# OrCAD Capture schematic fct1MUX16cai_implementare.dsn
size A
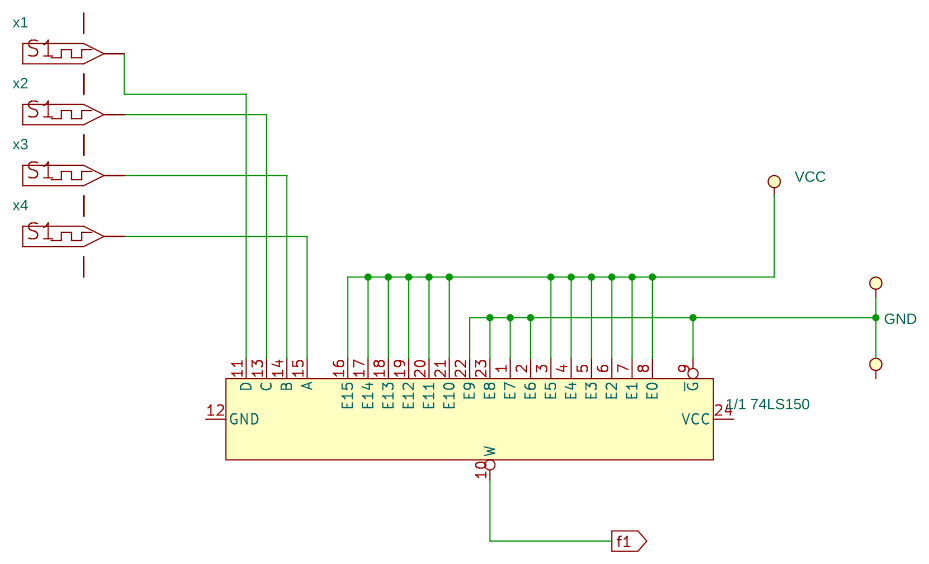
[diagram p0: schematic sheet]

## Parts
U1  1/1 74LS150  [DIP.100/24/W.300/L1.250]
x1  DigStim1
x2  DigStim1
x3  DigStim1
x4  DigStim1

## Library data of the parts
U1 = 74150
x1-x4 = DigStim1

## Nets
VCC: U1.3(E5) U1.4(E4) U1.5(E3) U1.6(E2) U1.7(E1) U1.8(E0) U1.16(E15) U1.17(E14) U1.18(E13) U1.19(E12) U1.20(E11) U1.21(E10) U1.24(VCC) x1.2(VCC) x2.2(VCC) x3.2(VCC) x4.2(VCC)
0: U1.1(E7) U1.2(E6) U1.9(~{G}) U1.12(GND) U1.22(E9) U1.23(E8) x1.3(GND) x2.3(GND) x3.3(GND) x4.3(GND)
f1: U1.10(W)
N14703: U1.11(D) x1.OUT
N14707: U1.13(C) x2.OUT
N14726: U1.14(B) x3.OUT
N14748: U1.15(A) x4.OUT
